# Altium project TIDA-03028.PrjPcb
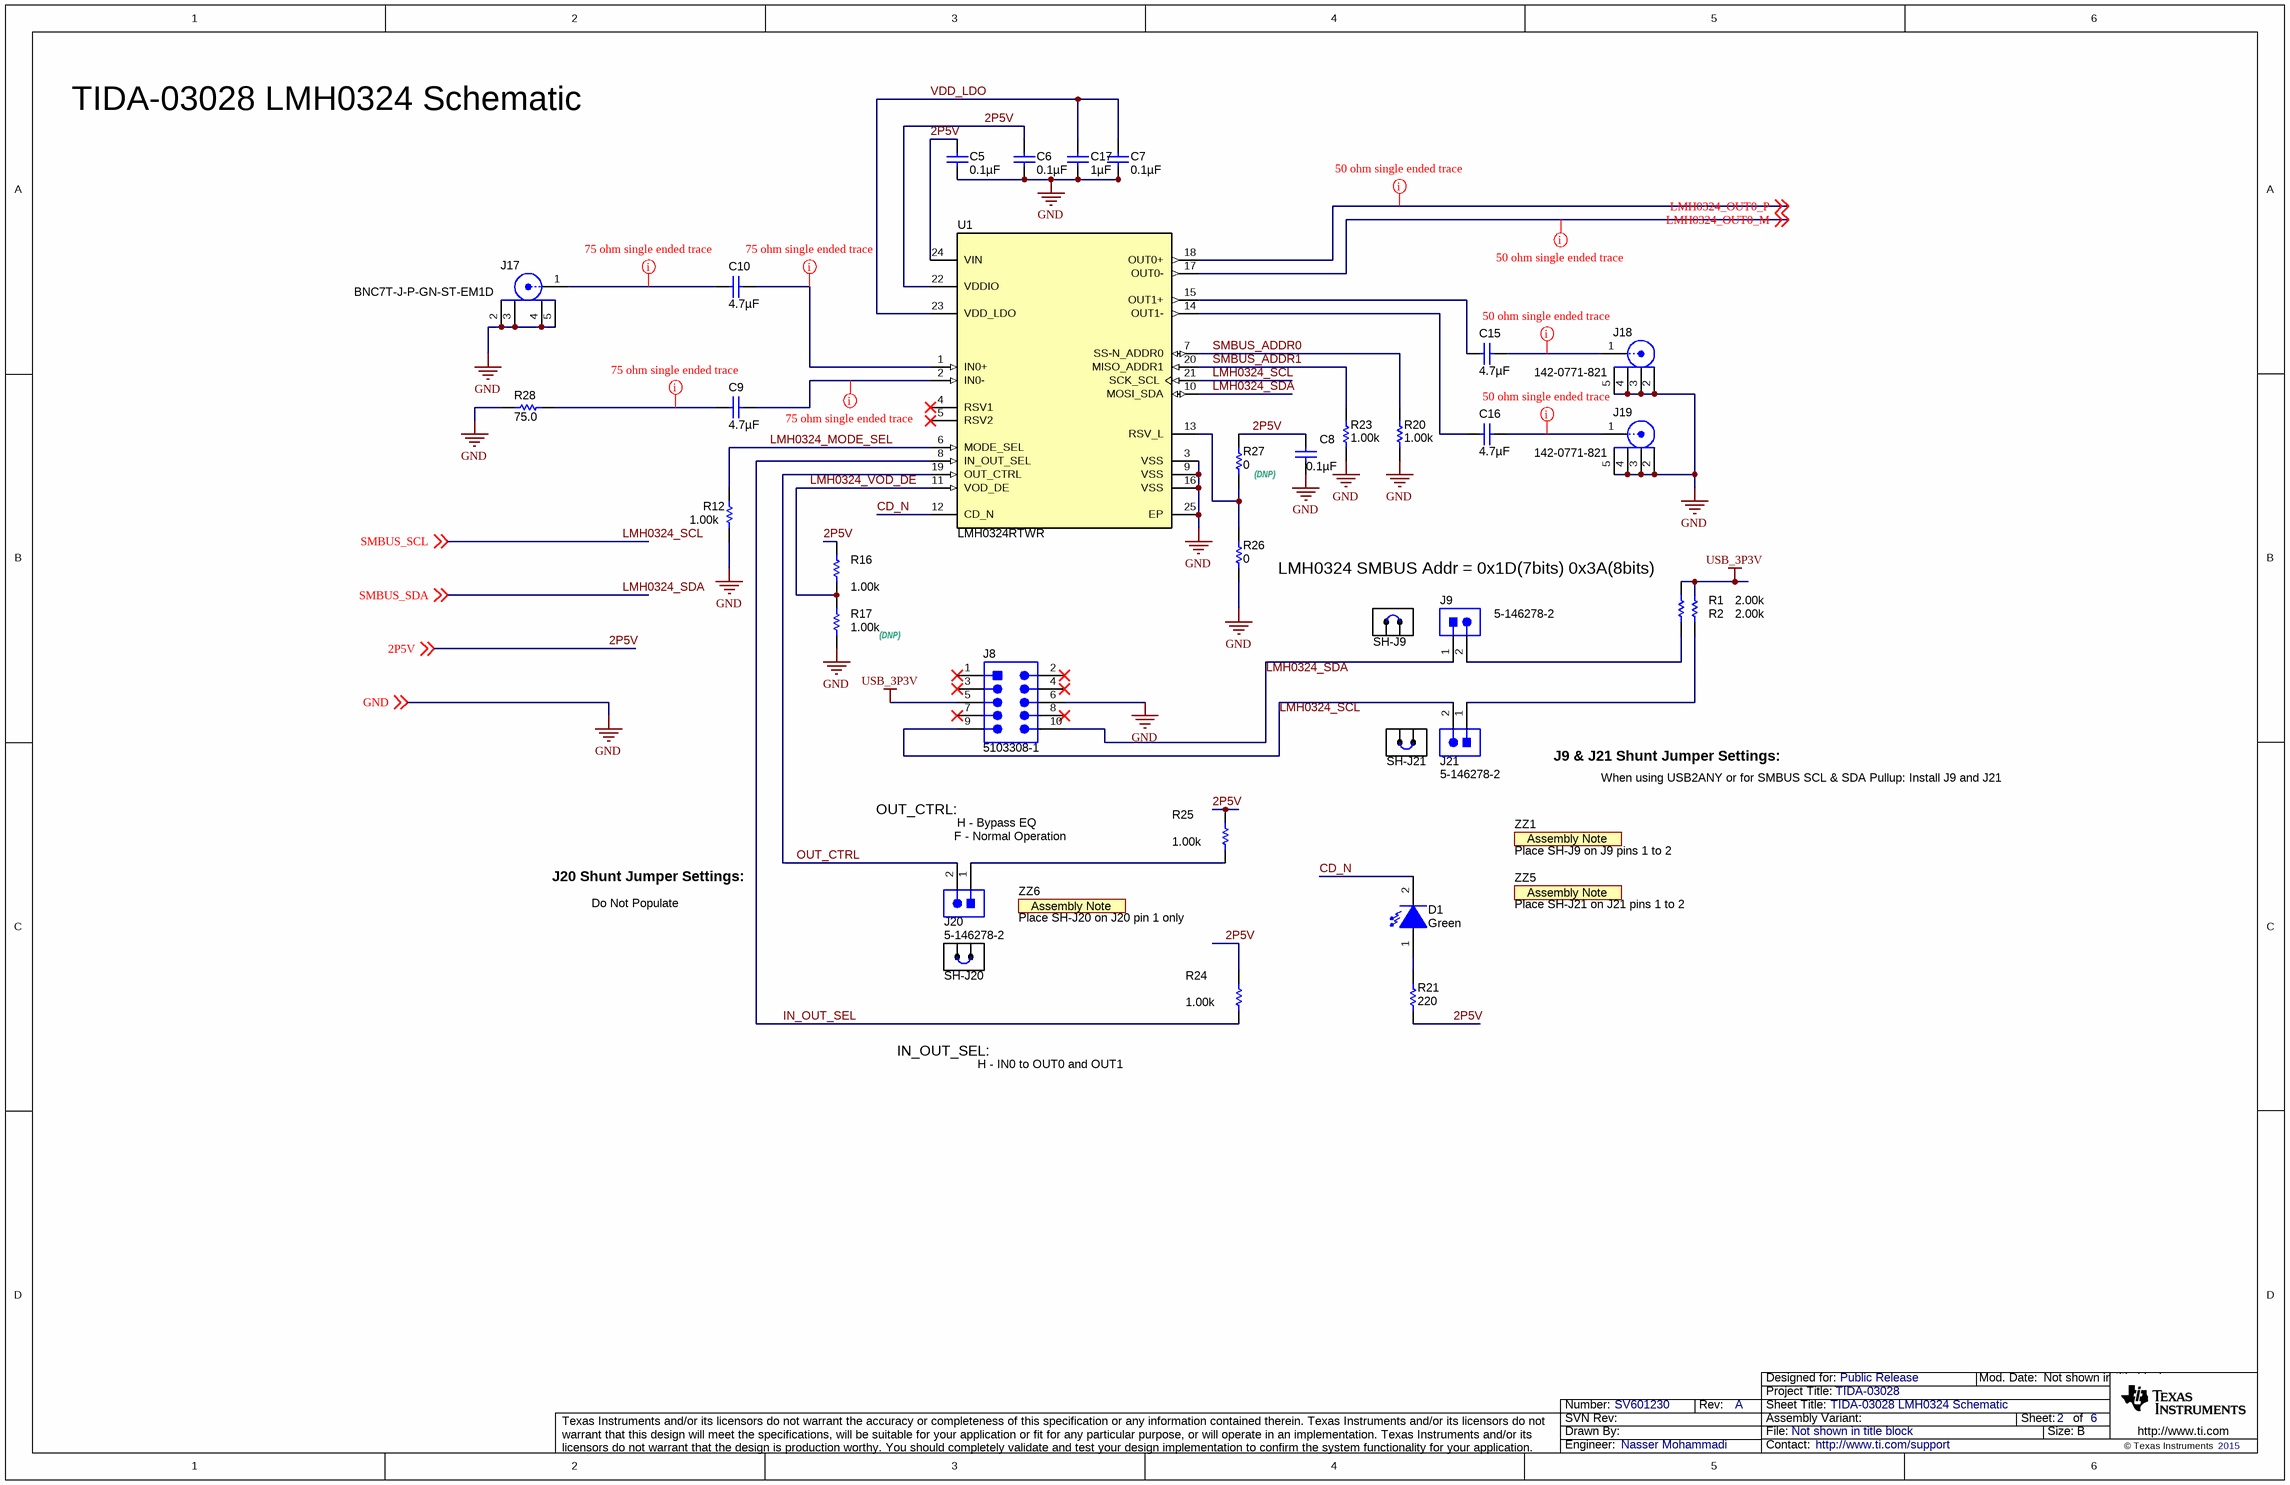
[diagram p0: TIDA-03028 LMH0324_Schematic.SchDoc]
TechSupport: http://www.ti.com/support; SCH_Rev: A; PRJ_Title: TIDA-03028; PRJ_Number: SV601230; PRJ_Engineer: Nasser Mohammadi; PRJ_Customer: Public Release; PCB_Rev: A; CopyrightYear: 2015
6 sheets, 129 parts. Net scope: global (net labels, ports and power ports of the same name join across sheets).
Sheets:
  TIDA-03028 LMH0324_Schematic.SchDoc
  TIDA-03028 USB_CNTRL.SchDoc
  TIDA-03028 LMH0318_Schematic.SchDoc
  TIDA-03028 Hardware.SchDoc
  TIDA-03028 Block Diagram.SchDoc
  TIDA-03028 Power.SchDoc

## Sheet TIDA-03028 LMH0324_Schematic.SchDoc: TIDA-03028 LMH0324 Schematic
size 431 x 279 mm; Date: Not shown in title block; ApprovedBy: Not shown in title block; CheckedBy: Not shown in title block; Author: Not shown in title block; CompanyName: Not shown in title block; Engineer: NasserM; Organization: Not shown in title block; Address1: Not shown in title block; Address2: Not shown in title block; Address3: Not shown in title block; Address4: Not shown in title block; DocumentNumber: 1; Revision: A; SheetNumber: 2; SheetTotal: 6; PageSetup: Record=PageOptions¦CenterHorizontal=True¦CenterVertical=True¦PrintScale=0.59¦XCorrection=1.00¦YCorrection=1.00¦PrintKind=0¦BorderSize=5000000¦LeftOffset=0¦BottomOffset=0¦Orientation=2¦PaperLength=1000¦PaperWidth=1000¦Scale=100¦PaperSource=15¦PrintQuality=600¦MediaType=1¦DitherType=10¦PaperKind=Letter¦PrintScaleMode=1

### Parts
C5  ValueDisplayed: 0.1µF  [0402]  (hidden comment: C1005X5R0J104K)
C6  ValueDisplayed: 0.1µF  [0402]  (hidden comment: C1005X5R0J104K)
C7  ValueDisplayed: 0.1µF  [0402]  (hidden comment: C1005X5R0J104K)
C8  ValueDisplayed: 0.1µF  [0402]  (hidden comment: C1005X5R0J104K)
C9  ValueDisplayed: 4.7µF  [0402S]  (hidden comment: C1005X5R1A475K050BC)
C10  ValueDisplayed: 4.7µF  [0402S]  (hidden comment: C1005X5R1A475K050BC)
C15  ValueDisplayed: 4.7µF  [0402S]  (hidden comment: C1005X5R1A475K050BC)
C16  ValueDisplayed: 4.7µF  [0402S]  (hidden comment: C1005X5R1A475K050BC)
C17  ValueDisplayed: 1µF  [0402]  (hidden comment: C1005X5R0J105M)
D1  value Green  [LED_SML-LX0603GW]  (hidden comment: SML-LX0603GW-TR)
J8  5103308-1  [CONN_5103308-1]
J9  5-146278-2  [TE_5-146278-2]
J17  BNC7T-J-P-GN-ST-EM1D  [SAMTEC_BNC7T-J-P-GN-ST-EM1D]
J18  142-0771-821  [Emerson_142-0771-821]
J19  142-0771-821  [Emerson_142-0771-821]
J20  5-146278-2  [TE_5-146278-2]
J21  5-146278-2  [TE_5-146278-2]
R1  value 2.00k  [0402]  (hidden comment: CRCW04022K00FKED)
R2  value 2.00k  [0402]  (hidden comment: CRCW04022K00FKED)
R12  value 1.00k  [0402]  (hidden comment: CRCW04021K00FKED)
R16  value 1.00k  [0402]  (hidden comment: Do Not Populate)
R17  value 1.00k  [0402]  (hidden comment: CRCW04021K00FKED)
R20  value 1.00k  [0402]  (hidden comment: CRCW04021K00FKED)
R21  value 220  [0402]  (hidden comment: CRCW0402220RJNED)
R23  value 1.00k  [0402]  (hidden comment: CRCW04021K00FKED)
R24  value 1.00k  [0402]  (hidden comment: CRCW04021K00FKED)
R25  value 1.00k  [0402]  (hidden comment: CRCW04021K00FKED)
R26  ValueDisplayed: 0  [0402]  (hidden comment: ERJ-2GE0R00X)
R27  ValueDisplayed: 0  [0402]  (hidden comment: Do Not Populate)
R28  value 75.0  [0402]  (hidden comment: CRCW040275R0FKED)
SH-J9  969102-0000-DA  [SNT-100-BK-G]  (value not drawn)
SH-J20  969102-0000-DA  [SNT-100-BK-G]  (value not drawn)
SH-J21  969102-0000-DA  [SNT-100-BK-G]  (value not drawn)
U1  LMH0324RTWR  [RTW0024A]
ZZ1  Place SH-J9 on J9 pins 1 to 2  [AssemblyNote]  (no BOM)
ZZ5  Place SH-J21 on J21 pins 1 to 2  [AssemblyNote]  (no BOM)
ZZ6  Place SH-J20 on J20 pin 1 only  [AssemblyNote]  (no BOM)

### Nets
2P5V: C5.1 C6.1 C8.1 R16.2 R21.1 R24.2 R25.2 R27.2 U1.22(VDDIO) U1.24(VIN) ; off-sheet 2P5V
GND: C5.2 C6.2 C7.2 C8.2 C17.2 J8.6 J17.2 J17.3 J17.4 J17.5 J18.2 J18.3 J18.4 J18.5 J19.2 J19.3 J19.4 J19.5 R12.1 R17.1 R20.1 R23.1 R26.1 R28.2 U1.3(VSS) U1.9(VSS) U1.16(VSS) U1.25(EP) ; off-sheet GND
USB_3P3V: J8.5 R1.2 R2.2
CD_N: D1.2(K) U1.12(CD_N)
IN_OUT_SEL: R24.1 U1.8(IN_OUT_SEL)
LMH0324_MODE_SEL: R12.2 U1.6(MODE_SEL)
LMH0324_OUT0_M: U1.17(OUT0-) ; off-sheet LMH0324_OUT0_M
LMH0324_OUT0_P: U1.18(OUT0+) ; off-sheet LMH0324_OUT0_P
LMH0324_SCL: J8.9 J21.2 U1.21(SCK_SCL) ; off-sheet SMBUS_SCL  [also labelled SMBUS_SCL]  [project net GPIO1/I2C_SCL]
LMH0324_SDA: J8.10 J9.1 U1.10(MOSI_SDA) ; off-sheet SMBUS_SDA  [also labelled SMBUS_SDA]  [project net GPIO0/I2C_SDA]
LMH0324_VOD_DE: R16.1 R17.2 U1.11(VOD_DE)
OUT_CTRL: J20.2 U1.19(OUT_CTRL)
SMBUS_ADDR0: R20.2 U1.7(SS-N_ADDR0)
SMBUS_ADDR1: R23.2 U1.20(MISO_ADDR1)
VDD_LDO: C7.1 C17.1 U1.23(VDD_LDO)
NetC9_1: C9.1 U1.2(IN0-)
NetC9_2: C9.2 R28.1
NetC10_1: C10.1 U1.1(IN0+)
NetC10_2: C10.2 J17.1
NetC15_1: C15.1 J18.1
NetC15_2: C15.2 U1.15(OUT1+)
NetC16_1: C16.1 J19.1
NetC16_2: C16.2 U1.14(OUT1-)
NetD1_1: D1.1(A) R21.2
NetJ9_2: J9.2 R1.1
NetJ20_1: J20.1 R25.1
NetJ21_1: J21.1 R2.1
NetR26_2: R26.2 R27.1 U1.13(RSV_L)

Not connected (* = marked no-connect by the designer): J8 1* 2* 3* 4* 7* 8*; U1 4(RSV1)* 5(RSV2)*

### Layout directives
rule Undefined: LMH0324_OUT0_M, LMH0324_OUT0_P, NetC9_1, NetC9_2, NetC10_1, NetC10_2, NetC15_1, NetC16_1

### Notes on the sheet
- TIDA-03028 LMH0324 Schematic
- (near R27) (DNP)
- LMH0324 SMBUS Addr = 0x1D(7bits) 0x3A(8bits)
- (DNP)
- J9 & J21 Shunt Jumper Settings:
- OUT_CTRL:
- H - Bypass EQ
- F - Normal Operation
- When using USB2ANY or for SMBUS SCL & SDA Pullup: Install J9 and J21
- Do Not Populate
- J20 Shunt Jumper Settings:
- IN_OUT_SEL:
- H - IN0 to OUT0 and OUT1

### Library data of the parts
C5-C8 = C1005X5R0J104K: CAP, CERM, 0.1uF, 6.3V, +/-10%, X5R, 0402; Manufacturer: TDK; Polarized: N; CompType: Capacitor; U/M: EA; Cap_F: 0.0000001; Tolerance_%: 10; ESR_Ohm: 0.0186; Value1: 0.0186 ohm; VDC_V: 6.3; TaMin_C: -55; TaMax_C: 85
C9 C10 C15 C16 = C1005X5R1A475K050BC: CAP, CERM, 4.7 µF, 10 V, +/- 10%, X5R, 0402; Manufacturer: TDK; Polarized: N; CompType: Capacitor; Value: 4.7uF; U/M: EA; Cap_F: 0.0000047; Tolerance_%: 10; Value1: Unknown; Value2: 10V; TaMin_C: -55; TaMax_C: 85; Cap_Case: 0402
C17 = C1005X5R0J105M: CAP, CERM, 1 µF, 6.3 V, +/- 20%, X5R, 0402; Manufacturer: TDK; Polarized: N; CompType: Capacitor; Value: 1uF; U/M: EA; Cap_F: 0.000001; Tolerance_%: 20; ESR_ohm: 0.0079; Value1: 0.0079 ohm; VDC_V: 6.3; Value2: 6.3V; TaMin_C: -55; TaMax_C: 85
D1 = SML-LX0603GW-TR: LED, Green, SMD; Manufacturer: Lumex; Vf_V: 2.2; Value2: 2.2V; Io_A: 0.02; Tjmax_C: 85; Value1: W; U/M: EA
J8 = 5103308-1: Header (shrouded), 100mil, 5x2, Gold, TH; Manufacturer: TE Connectivity; SymbolCreator: a0412235; U/M: EA
J9 J20 J21 = 5-146278-2: Header, 100mil, 2x1, Tin, TH; Manufacturer: TE Connectivity; SymbolCreator: a0412235; U/M: EA
J17 = BNC7T-J-P-GN-ST-EM1D: Connector, BNC Edge Mount, SMD; Manufacturer: Samtec; SymbolCreator: Altium; U/M: EA
J18 J19 = 142-0771-821: Connector, TH, End launch SMA 50 ohm; Manufacturer: Emerson Network Power; SymbolCreator: X0208326; U/M: EA
R1 R2 = CRCW04022K00FKED: RES, 2.00k ohm, 1%, 0.063W, 0402; Manufacturer: Vishay-Dale; CompType: Resistor; Res_ohm: 2000; Value_Code: 2k00; Tolerance_%: 1; Power_W: 0.063; VDC_V: 50; TempCo: 100 ppm/C; EIA_Code: E96; U/M: EA
R12 R16 R17 R20 R23-R25 = CRCW04021K00FKED: RES, 1.00k ohm, 1%, 0.063W, 0402; Manufacturer: Vishay-Dale; CompType: Resistor; Res_ohm: 1000; Value_Code: 1k00; Tolerance_%: 1; Power_W: 0.063; VDC_V: 50; TempCo: 100 ppm/C; EIA_Code: E96; U/M: EA
R21 = CRCW0402220RJNED: RES, 220 ohm, 5%, 0.063W, 0402; Manufacturer: Vishay-Dale; CompType: Resistor; Value_Code: 220R; Tolerance_%: 5; Power_W: 0.063; VDC_V: 50; TempCo: 200 ppm/C; EIA_Code: E24; U/M: EA
R26 R27 = ERJ-2GE0R00X: RES, 0, 5%, 0.063 W, 0402; Manufacturer: Panasonic; CompType: Resistor; Value_Code: 0000; Tolerance_%: 5; Power_W: 0.063; Value2: 0.063W; VDC_V: 50; TempCo: 600 ppm/C; EIA_Code: E24; U/M: EA; Value: 0; AEC Category: Q200
R28 = CRCW040275R0FKED: RES, 75.0 ohm, 1%, 0.063W, 0402; Manufacturer: Vishay-Dale; CompType: Resistor; Res_ohm: 75; Value_Code: 75R0; Tolerance_%: 1; Power_W: 0.063; VDC_V: 50; TempCo: 100 ppm/C; EIA_Code: E96; U/M: EA
SH-J9 SH-J20 SH-J21 = 969102-0000-DA: Shunt, 100mil, Gold plated, Black; Manufacturer: 3M; Alternate Manufacturer: Samtec; Value: 1x2; Note: You can "mate" this to a header by matching the designator.  i.e. use SH-J3 for header J3
U1 = LMH0324RTWR: 3G HD/SD SDI Adaptive Cable Equalizer, RTW0024A; Alternate PartNumber: LMH0324RTWT; Manufacturer: Texas Instruments; SymbolCreator: Altium; CompType: IC; U/M: EA
ZZ1 ZZ5 ZZ6 = AssemblyNote: SymbolCreator: codlsc

## Sheet TIDA-03028 USB_CNTRL.SchDoc: TIDA-03028 - USB_CNTRL
size 431 x 279 mm; Date: Not shown in title block; ApprovedBy: Not shown in title block; CheckedBy: Not shown in title block; Author: Not shown in title block; CompanyName: Not shown in title block; Engineer: Not shown in title block; Organization: Not shown in title block; Address1: Not shown in title block; Address2: Not shown in title block; Address3: Not shown in title block; Address4: Not shown in title block; DocumentNumber: 1; Revision: Use project parameter SCH_Rev; SheetNumber: 4; SheetTotal: 6; PageSetup: Record=PageOptions¦CenterHorizontal=True¦CenterVertical=True¦PrintScale=1.00¦XCorrection=1.00¦YCorrection=1.00¦PrintKind=0¦BorderSize=5000000¦LeftOffset=0¦BottomOffset=0¦Orientation=2¦PaperLength=1000¦PaperWidth=1000¦Scale=100¦PaperSource=15¦PrintQuality=600¦MediaType=1¦DitherType=10¦PaperKind=Letter¦PrintScaleMode=1
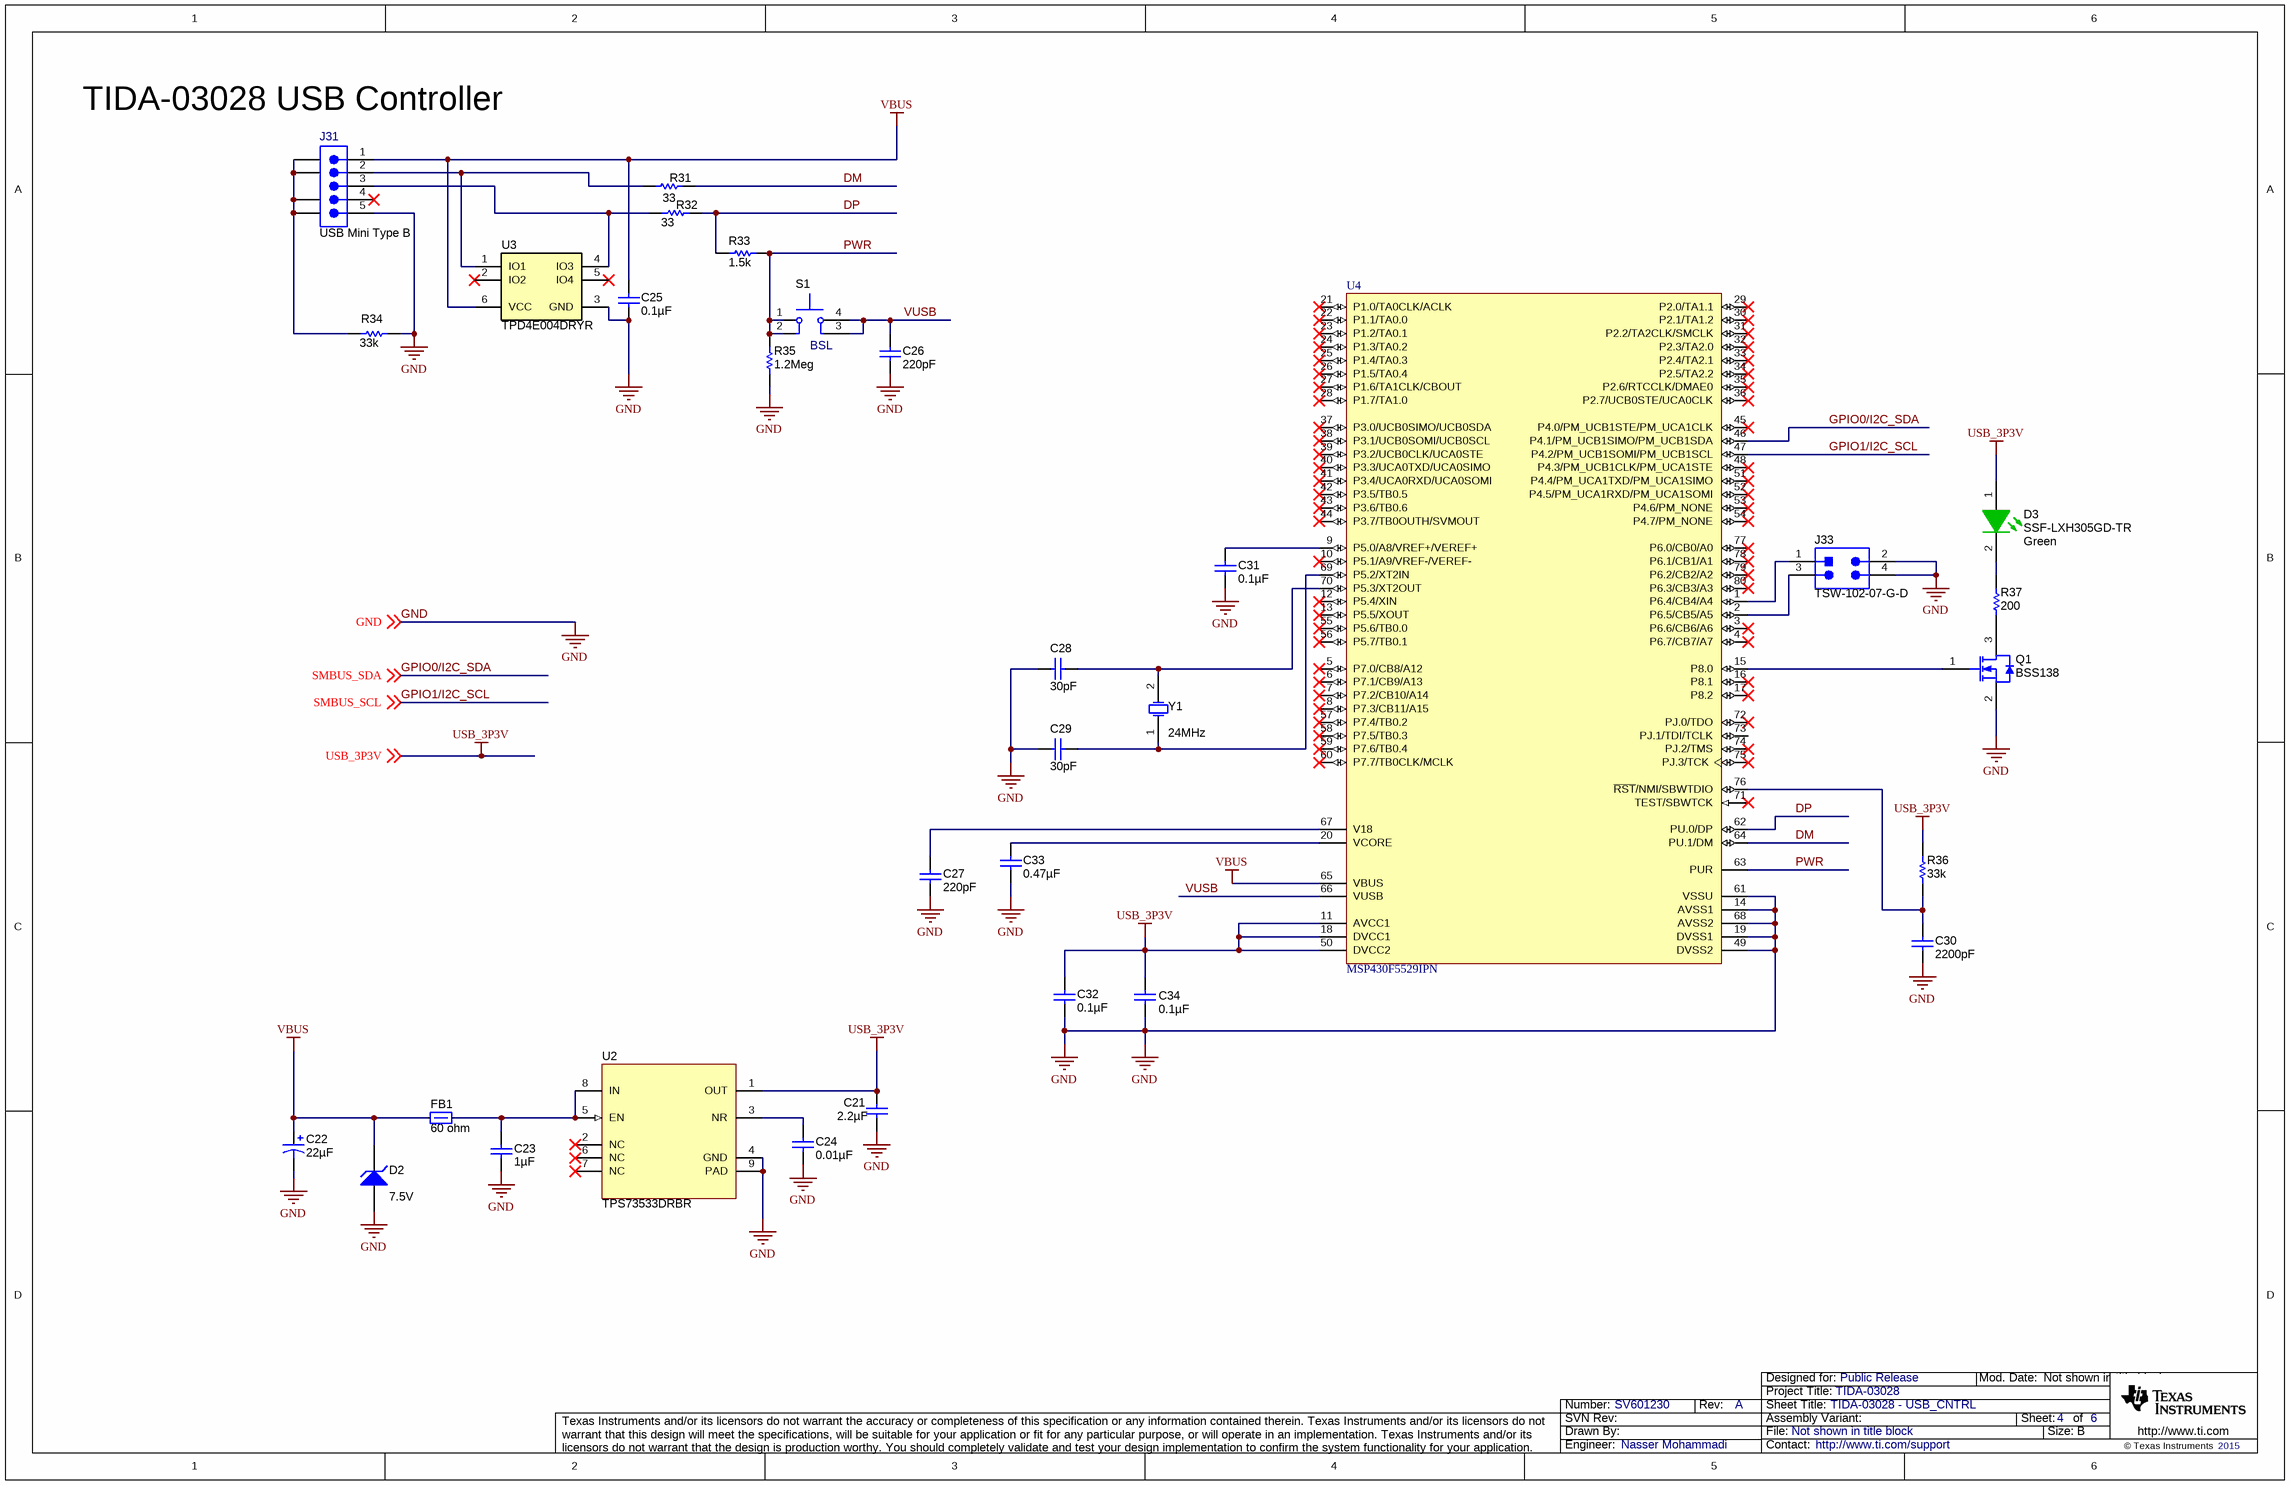
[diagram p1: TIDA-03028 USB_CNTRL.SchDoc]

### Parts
C21  ValueDisplayed: 2.2µF  [C0805]  (hidden comment: 0805YD225KAT2A)
C22  ValueDisplayed: 22µF  [CAPSMT_62_E55]  (hidden comment: EMVE100ADA220ME55G)
C23  ValueDisplayed: 1µF  [0805_HV]  (hidden comment: 0805YD105KAT2A)
C24  ValueDisplayed: 0.01µF  [C603]  (hidden comment: C1608X7R1H103K)
C25  ValueDisplayed: 0.1µF  [C603]  (hidden comment: 0603YC104JAT2A)
C26  ValueDisplayed: 220pF  [C603]  (hidden comment: 06035A221FAT2A)
C27  ValueDisplayed: 220pF  [C603]  (hidden comment: 06035A221FAT2A)
C28  ValueDisplayed: 30pF  [C603]  (hidden comment: GRM1885C2A300JA01D)
C29  ValueDisplayed: 30pF  [C603]  (hidden comment: GRM1885C2A300JA01D)
C30  ValueDisplayed: 2200pF  [C603]  (hidden comment: C0603X222K5RACTU)
C31  ValueDisplayed: 0.1µF  [C603]  (hidden comment: 0603YC104JAT2A)
C32  ValueDisplayed: 0.1µF  [C603]  (hidden comment: 0603YC104JAT2A)
C33  ValueDisplayed: 0.47µF  [C603]  (hidden comment: GRM188R71A474KA61D)
C34  ValueDisplayed: 0.1µF  [C603]  (hidden comment: 0603YC104JAT2A)
D2  value 7.5V  [SMB]  (hidden comment: 1SMB5922BT3G)
D3  SSF-LXH305GD-TR  value Green  [SSF-LXH305GD_Green]
FB1  value 60 ohm  [0603]  (hidden comment: BK1608HS600-T)
J31  USB Mini Type B  [CONN_USB-Mini-B-1734035-2]
J33  TSW-102-07-G-D  [TSW-102-07-G-D]
Q1  BSS138  [SOT-23]
R31  value 33  [0402]  (hidden comment: CRCW040233R0JNED)
R32  value 33  [0402]  (hidden comment: CRCW040233R0JNED)
R33  value 1.5k  [0402]  (hidden comment: CRCW04021K50JNED)
R34  value 33k  [0402]  (hidden comment: CRCW040233K0JNED)
R35  value 1.2Meg  [R603]  (hidden comment: CRCW06031M20JNEA)
R36  value 33k  [0402]  (hidden comment: CRCW040233K0JNED)
R37  value 200  [R603]  (hidden comment: CRCW0603200RFKEA)
S1  EVQ-PSD02K  [SW_EVQ-PSD02K]  (value not drawn)
U2  TPS73533DRBR  [DRB0008A]
U3  TPD4E004DRYR  [DRY0006A]
U4  MSP430F5529IPN  [PN0080A_N]
Y1  Frequency: 24MHz  [XTAL_CSM-7X]  (hidden comment: ECS-240-20-5PX-TR)

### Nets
GND: C21.1 C22.2(-) C23.1 C24.1 C25.1 C26.1 C27.1 C28.2 C29.2 C30.1 C31.1 C32.1 C33.1 C34.1 D2.2(A) J31.5 J33.2 J33.4 Q1.2(S) R34.1 R35.1 U2.4(GND) U2.9(PAD) U3.3(GND) U4.14(AVSS1) U4.19(DVSS1) U4.49(DVSS2) U4.61(VSSU) U4.68(AVSS2) ; off-sheet GND
USB_3P3V: C21.2 C32.2 C34.2 D3.1(A) R36.1 U2.1(OUT) U4.11(AVCC1) U4.18(DVCC1) U4.50(DVCC2) ; off-sheet USB_3P3V
VBUS: C22.1(+) C25.2 D2.1(K) FB1.1 J31.1 U3.6(VCC) U4.65(VBUS)
DM: R31.1 U4.64(PU.1/DM)
DP: R32.1 R33.2 U4.62(PU.0/DP)
GPIO0/I2C_SDA: U4.46(P4.1/PM_UCB1SIMO/PM_UCB1SDA) ; off-sheet SMBUS_SDA  [also labelled SMBUS_SDA]
GPIO1/I2C_SCL: U4.47(P4.2/PM_UCB1SOMI/PM_UCB1SCL) ; off-sheet SMBUS_SCL  [also labelled SMBUS_SCL]
PWR: R33.1 R35.2 S1.1 S1.2 U4.63(PUR)
VUSB: C26.2 S1.3 S1.4 U4.66(VUSB)
NetC23_2: C23.2 FB1.2 U2.5(EN) U2.8(IN)
NetC24_2: C24.2 U2.3(NR)
NetC27_2: C27.2 U4.67(V18)
NetC28_1: C28.1 U4.70(P5.3/XT2OUT) Y1.2(OSC2)
NetC29_1: C29.1 U4.69(P5.2/XT2IN) Y1.1(OSC1)
NetC30_2: C30.2 R36.2 U4.76(~{RST}/NMI/SBWTDIO)
NetC31_2: C31.2 U4.9(P5.0/A8/VREF+/VEREF+)
NetC33_2: C33.2 U4.20(VCORE)
NetD3_2: D3.2(K) R37.2
NetJ31_2: J31.2 R31.2 U3.1(IO1)
NetJ31_3: J31.3 R32.2 U3.4(IO3)
NetJ31_6: J31.6(GND) J31.7(GND) J31.8(GND) J31.9(GND) R34.2
NetJ33_1: J33.1 U4.1(P6.4/CB4/A4)
NetJ33_3: J33.3 U4.2(P6.5/CB5/A5)
NetQ1_1: Q1.1(G) U4.15(P8.0)
NetQ1_3: Q1.3(D) R37.1

Not connected (* = marked no-connect by the designer): J31 4*; U2 2(NC)* 6(NC)* 7(NC)*; U3 2(IO2)* 5(IO4)*; U4 3(P6.6/CB6/A6)* 4(P6.7/CB7/A7)* 5(P7.0/CB8/A12)* 6(P7.1/CB9/A13)* 7(P7.2/CB10/A14)* 8(P7.3/CB11/A15)* 10(P5.1/A9/VREF-/VEREF-)* 12(P5.4/XIN)* 13(P5.5/XOUT)* 16(P8.1)* 17(P8.2)* 21(P1.0/TA0CLK/ACLK)* 22(P1.1/TA0.0)* 23(P1.2/TA0.1)* 24(P1.3/TA0.2)* 25(P1.4/TA0.3)* 26(P1.5/TA0.4)* 27(P1.6/TA1CLK/CBOUT)* 28(P1.7/TA1.0)* 29(P2.0/TA1.1)* 30(P2.1/TA1.2)* 31(P2.2/TA2CLK/SMCLK)* 32(P2.3/TA2.0)* 33(P2.4/TA2.1)* 34(P2.5/TA2.2)* 35(P2.6/RTCCLK/DMAE0)* 36(P2.7/UCB0STE/UCA0CLK)* 37(P3.0/UCB0SIMO/UCB0SDA)* 38(P3.1/UCB0SOMI/UCB0SCL)* 39(P3.2/UCB0CLK/UCA0STE)* 40(P3.3/UCA0TXD/UCA0SIMO)* 41(P3.4/UCA0RXD/UCA0SOMI)* 42(P3.5/TB0.5)* 43(P3.6/TB0.6)* 44(P3.7/TB0OUTH/SVMOUT)* 45(P4.0/PM_UCB1STE/PM_UCA1CLK)* 48(P4.3/PM_UCB1CLK/PM_UCA1STE)* 51(P4.4/PM_UCA1TXD/PM_UCA1SIMO)* 52(P4.5/PM_UCA1RXD/PM_UCA1SOMI)* 53(P4.6/PM_NONE)* 54(P4.7/PM_NONE)* 55(P5.6/TB0.0)* 56(P5.7/TB0.1)* 57(P7.4/TB0.2)* 58(P7.5/TB0.3)* 59(P7.6/TB0.4)* 60(P7.7/TB0CLK/MCLK)* 71(TEST/SBWTCK)* 72(PJ.0/TDO)* 73(PJ.1/TDI/TCLK) 74(PJ.2/TMS)* 75(PJ.3/TCK)* 77(P6.0/CB0/A0)* 78(P6.1/CB1/A1)* 79(P6.2/CB2/A2)* 80(P6.3/CB3/A3)*

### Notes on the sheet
- (near J31) TIDA-03028 USB Controller
- (near S1) BSL

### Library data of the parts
C21 = 0805YD225KAT2A: CAP, CERM, 2.2uF, 16V, +/-10%, X5R, 0805; Manufacturer: AVX; Polarized: N; CompType: Capacitor; U/M: EA; Cap_F: 0.0000022; Tolerance_%: 10; ESR_Ohm: 0.009; Value1: 0.009 ohm; VDC_V: 16; TaMin_C: -55; TaMax_C: 85; Cap_Case: 0805
C22 = EMVE100ADA220ME55G: CAP ALUM 22UF 10V 20% SMD; Manufacturer: Panasonic - ECG; Polarized: Y; CompType: Capacitor; U/M: EA; Cap_F: 0.000022; Tolerance_%: 20; VDC_V: 10; IRMS_A: 0.03; TaMin_C: -40; TaMax_C: 105; Cap_Case: E55
C23 = 0805YD105KAT2A: CAP, CERM, 1 µF, 16 V, +/- 10%, X5R, 0805; Manufacturer: AVX; Polarized: N; CompType: Capacitor; Value: 1uF; U/M: EA; Cap_F: 0.000001; Tolerance_%: 10; ESR_ohm: 0.012; Value1: 0.012 ohm; VDC_V: 16; Value2: 16V; TaMin_C: -55; TaMax_C: 85; Cap_Case: 0805; AEC Category: Q200
C24 = C1608X7R1H103K: CAP, CERM, 0.01uF, 50V, +/-10%, X7R, 0603; Manufacturer: TDK; Polarized: N; CompType: Capacitor; U/M: EA; Cap_F: 0.00000001; Tolerance_%: 10; ESR_Ohm: 0.0539; Value1: 0.0539 ohm; VDC_V: 50; TaMin_C: -55; TaMax_C: 125; Cap_Case: 0603
C25 C31 C32 C34 = 0603YC104JAT2A: CAP, CERM, 0.1uF, 16V, +/-5%, X7R, 0603; Manufacturer: AVX; Polarized: N; CompType: Capacitor; U/M: EA; Cap_F: 0.0000001; Tolerance_%: 5; ESR_Ohm: 0.039; Value1: 0.039 ohm; VDC_V: 16; TaMin_C: -55; TaMax_C: 125; Cap_Case: 0603
C26 C27 = 06035A221FAT2A: CAP, CERM, 220pF, 50V, +/-1%, C0G/NP0, 0603; Manufacturer: AVX; Polarized: N; CompType: Capacitor; U/M: EA; Cap_F: 0.00000000022; Tolerance_%: 1; ESR_Ohm: 0.083; Value1: 0.083 ohm; VDC_V: 50; TaMin_C: -55; TaMax_C: 125; Cap_Case: 0603
C28 C29 = GRM1885C2A300JA01D: CAP, CERM, 30pF, 100V, +/-5%, C0G/NP0, 0603; Manufacturer: MuRata; Polarized: N; CompType: Capacitor; U/M: EA; Cap_F: 0.00000000003; Tolerance_%: 5; VDC_V: 100; TaMin_C: -55; TaMax_C: 125; Cap_Case: 0603
C30 = C0603X222K5RACTU: CAP, CERM, 2200pF, 50V, +/-10%, X7R, 0603; Manufacturer: Kemet; Polarized: N; CompType: Capacitor; U/M: EA; Cap_F: 0.0000000022; Tolerance_%: 10; VDC_V: 50; TaMin_C: -55; TaMax_C: 125; Cap_Case: 0603
C33 = GRM188R71A474KA61D: CAP, CERM, 0.47uF, 10V, +/-10%, X7R, 0603; Manufacturer: MuRata; Polarized: N; CompType: Capacitor; U/M: EA; Cap_F: 0.00000047; Tolerance_%: 10; TaMin_C: -55; TaMax_C: 125; Cap_Case: 0603
D2 = 1SMB5922BT3G: Diode, Zener, 7.5 V, 550 mW, SMB; Manufacturer: ON Semiconductor; SymbolCreator: a0412235; U/M: EA; Power_W: 0.55; Vz_V: 7.5; Value1: 0.55W; RJA_CperW: 226
D3 = SSF-LXH305GD-TR: LED, Green, SMD; Manufacturer: Lumex; SymbolCreator: Altium; Vf_V: 2.2; Value2: 2.2V; Io_A: 0.02; Vr_V: 5; Ir_A: 0.0001; Tjmax_C: 85; Value1: W; Angle: 60; U/M: EA
FB1 = BK1608HS600-T: Ferrite Bead, 60 ohm @ 100 MHz, 0.8 A, 0603; Manufacturer: Taiyo Yuden; Imax_A: 0.8; DCR_ohm: 0.1; Value1: 0.1 ohm; Value2: 0.8A; ZTyp@100MHz_Ohm: 60
J31 = 1734035-2: Connector, Receptacle, Mini-USB Type B, R/A, Top Mount SMT; Manufacturer: TE Connectivity; SymbolCreator: A0412235; U/M: EA
J33 = TSW-102-07-G-D: Header, 100mil, 2x2, Gold, TH; Manufacturer: Samtec; SymbolCreator: a0412235; U/M: EA
Q1 = BSS138: MOSFET, N-CH, 50 V, 0.22 A, SOT-23; Manufacturer: Fairchild Semiconductor; Alternate Manufacturer: None; U/M: EA; ChType: N; Value: 50V; VdsMax_V: 50; Value1: 6 ohm; Rdson45_ohm: 6; Value2: 1.7 nC; QgTyp_nC: 1.7; Vgs_V: 20; IdsMax_A: 0.22
R31 R32 = CRCW040233R0JNED: RES, 33 ohm, 5%, 0.063W, 0402; Manufacturer: Vishay-Dale; CompType: Resistor; Value_Code: 33R0; Tolerance_%: 5; Power_W: 0.063; VDC_V: 50; TempCo: 200 ppm/C; EIA_Code: E24; U/M: EA
R33 = CRCW04021K50JNED: RES, 1.5k ohm, 5%, 0.063W, 0402; Manufacturer: Vishay-Dale; CompType: Resistor; Res_ohm: 1500; Value_Code: 1k50; Tolerance_%: 5; Power_W: 0.063; VDC_V: 50; TempCo: 200 ppm/C; EIA_Code: E24; U/M: EA
R34 R36 = CRCW040233K0JNED: RES, 33k ohm, 5%, 0.063W, 0402; Manufacturer: Vishay-Dale; CompType: Resistor; Res_ohm: 33000; Value_Code: 33k0; Tolerance_%: 5; Power_W: 0.063; VDC_V: 50; TempCo: 200 ppm/C; EIA_Code: E24; U/M: EA
R35 = CRCW06031M20JNEA: RES, 1.2Meg ohm, 5%, 0.1W, 0603; Manufacturer: Vishay-Dale; CompType: Resistor; Res_ohm: 1200000; Value_Code: 1M20; Tolerance_%: 5; Power_W: 0.1; VDC_V: 75; TempCo: 200 ppm/C; EIA_Code: E24; U/M: EA
R37 = CRCW0603200RFKEA: RES, 200 ohm, 1%, 0.1W, 0603; Manufacturer: Vishay-Dale; CompType: Resistor; Value_Code: 200R; Tolerance_%: 1; Power_W: 0.1; VDC_V: 75; TempCo: 100 ppm/C; EIA_Code: E96; U/M: EA
S1 = EVQ-PSD02K: Switch, Tactile, SPST-NO, SMT; Manufacturer: Panasonic; SymbolCreator: a0799628; VDC_V: 12; SwitchFunction: Off-Mom; PositionCount: 1; CurrentRating_mA: 50
U2 = TPS73533DRBR: 500mA, Low Quiescent Current, Ultra-Low Noise, High PSRR Low-Dropout Linear Regulator, DRB0008A; Manufacturer: Texas Instruments; Alternate PartNumber: TPS73533DRBT; SymbolCreator: Altium; CompType: IC; U/M: EA
U3 = TPD4E004DRYR: ESD-Protection Array for High-Speed Data Interfaces, 4 Channels, -40 to +85 degC, 6-pin SON (DRY), Green (RoHS & no Sb/Br); Manufacturer: Texas Instruments; Alternate PartNumber: Equivalent; 1394 / Firewire: TRUE; Breakdown Voltage(Min)(V): 6; IEC 61000-4-2 Air-Gap(+/- kV): 12; IEC 61000-4-2 Contact(+/- kV): 8; IO Capacitance(Typ)(pF): 1.6; IO Leakage Current(nA): 1; SubFamily: ESD Solution
U4 = MSP430F5529IPN: 25 MHz Mixed Signal Microcontroller with 128 KB Flash, 8192 B SRAM and 63 GPIOs, -40 to 85 degC, 80-pin QFP (PN), Green (RoHS & no Sb/Br); Manufacturer: Texas Instruments; Alternate PartNumber: Equivalent; ADC: 12-bit SAR; ADC Channels: 16; Brown Out Reset: Yes; DMA: 3; Flash(KB): 128; Frequency(MHz): 25; GPIO: 63; Multiplier: 32x32; Pin/Package: 0DIESALE, 80LQFP; SRAM(B): 8192; SubFamily: 5 Series; Timers - 16-bit: 4; USB: 1; USCI_A (UART/LIN/IrDA/SPI): 2
Y1 = ECS-240-20-5PX-TR: Crystal, 24.000MHz, 20pF, SMD; Manufacturer: ECS Inc.; SymbolCreator: a0412235; U/M: EA; TaMin_C: -10; TaMax_C: 70; Frequency Stability: ±50ppm

## Sheet TIDA-03028 LMH0318_Schematic.SchDoc: TIDA-03028 LMH0318_Schematic
size 431 x 279 mm; Date: Not shown in title block; ApprovedBy: Not shown in title block; CheckedBy: Not shown in title block; Author: Not shown in title block; CompanyName: Not shown in title block; Engineer: Nasser; Organization: Not shown in title block; Address1: Not shown in title block; Address2: Not shown in title block; Address3: Not shown in title block; Address4: Not shown in title block; DocumentNumber: 1; Revision: Use project parameter SCH_Rev; SheetNumber: 3; SheetTotal: 6; PageSetup: Record=PageOptions¦CenterHorizontal=True¦CenterVertical=True¦PrintScale=1.00¦XCorrection=1.00¦YCorrection=1.00¦PrintKind=0¦BorderSize=5000000¦LeftOffset=0¦BottomOffset=0¦Orientation=2¦PaperLength=1000¦PaperWidth=1000¦Scale=100¦PaperSource=15¦PrintQuality=600¦MediaType=1¦DitherType=10¦PaperKind=Letter¦PrintScaleMode=1
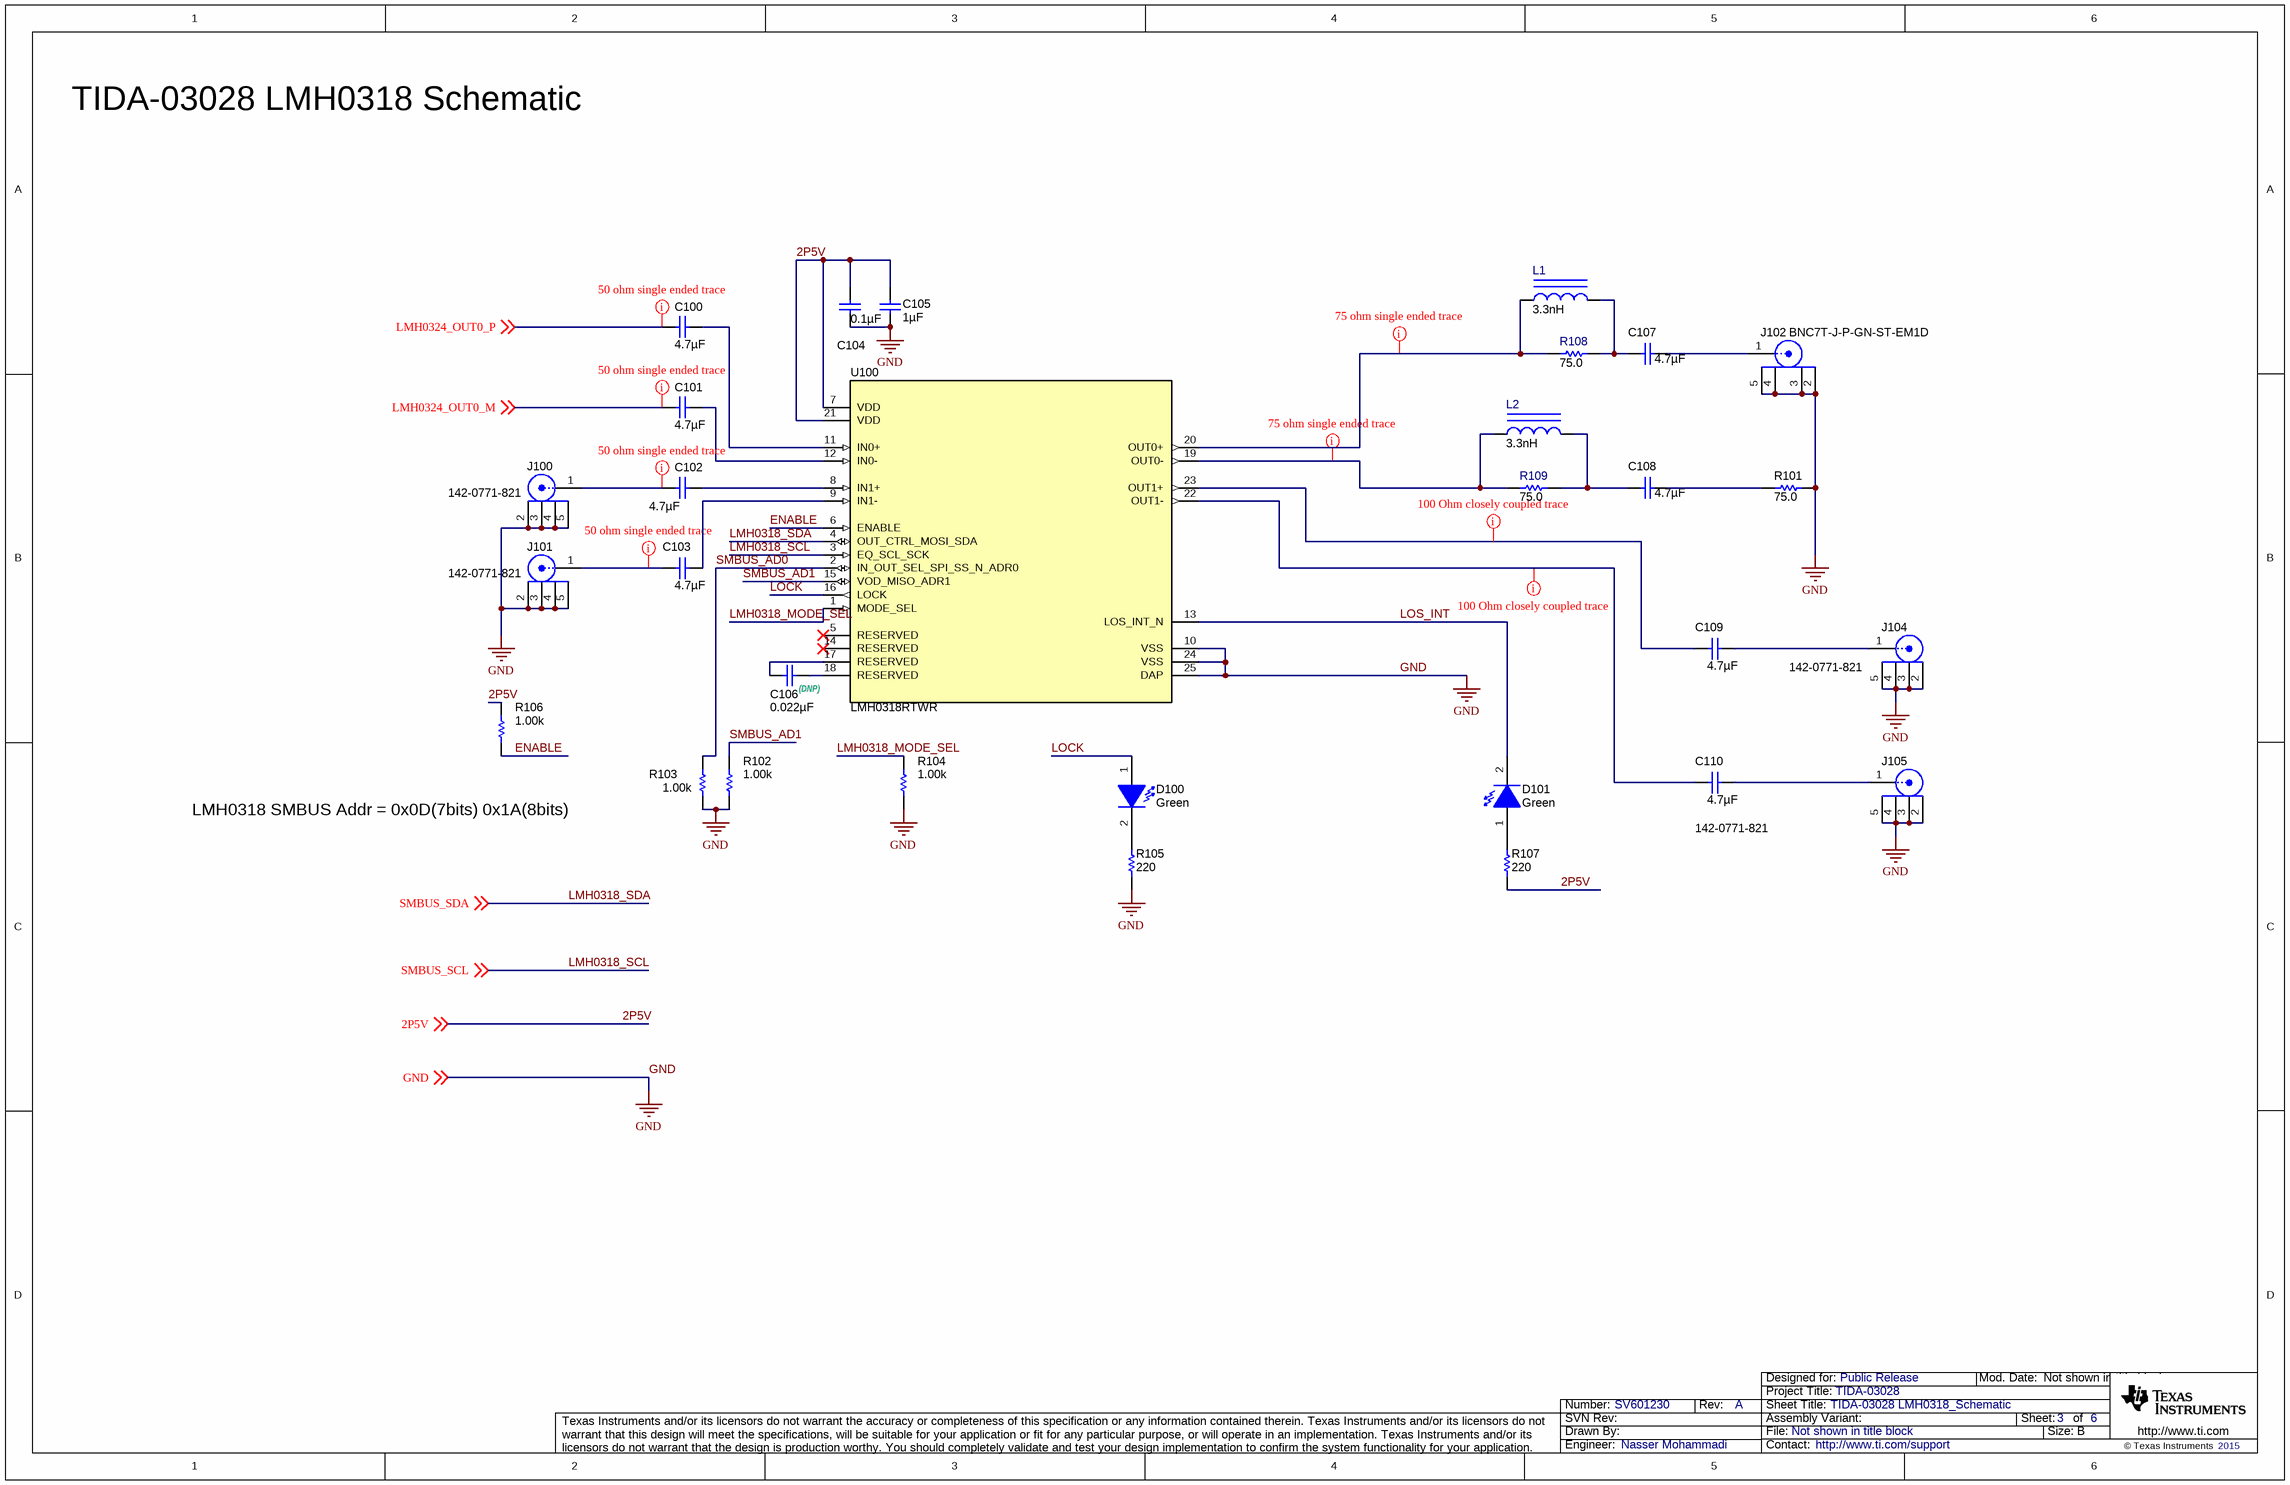
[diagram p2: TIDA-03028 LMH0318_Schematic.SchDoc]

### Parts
C100  ValueDisplayed: 4.7µF  [0402]  (hidden comment: C1005X5R0J475M050BC)
C101  ValueDisplayed: 4.7µF  [0402]  (hidden comment: C1005X5R0J475M050BC)
C102  ValueDisplayed: 4.7µF  [0402]  (hidden comment: C1005X5R0J475M050BC)
C103  ValueDisplayed: 4.7µF  [0402]  (hidden comment: C1005X5R0J475M050BC)
C104  ValueDisplayed: 0.1µF  [0402]  (hidden comment: C1005X5R0J104K)
C105  ValueDisplayed: 1µF  [0402]  (hidden comment: C1005X5R0J105M)
C106  ValueDisplayed: 0.022µF  [0402]  (hidden comment: Do Not Populate)
C107  ValueDisplayed: 4.7µF  [0402]  (hidden comment: C1005X5R0J475M050BC)
C108  ValueDisplayed: 4.7µF  [0402]  (hidden comment: C1005X5R0J475M050BC)
C109  ValueDisplayed: 4.7µF  [0402]  (hidden comment: C1005X5R0J475M050BC)
C110  ValueDisplayed: 4.7µF  [0402]  (hidden comment: C1005X5R0J475M050BC)
D100  value Green  [LED_SML-LX0603GW]  (hidden comment: SML-LX0603GW-TR)
D101  value Green  [LED_SML-LX0603GW]  (hidden comment: SML-LX0603GW-TR)
J100  142-0771-821  [Emerson_142-0771-821]
J101  142-0771-821  [Emerson_142-0771-821]
J102  BNC7T-J-P-GN-ST-EM1D  [SAMTEC_BNC7T-J-P-GN-ST-EM1D]
J104  142-0771-821  [Emerson_142-0771-821]
J105  142-0771-821  [Emerson_142-0771-821]
L1  ValueDisplayed: 3.3nH  [IND_LQG15H]  (hidden comment: LQG15HS3N3S02D)
L2  ValueDisplayed: 3.3nH  [IND_LQG15H]  (hidden comment: LQG15HS3N3S02D)
R101  value 75.0  [0402]  (hidden comment: CRCW040275R0FKED)
R102  value 1.00k  [0402]  (hidden comment: CRCW04021K00FKED)
R103  value 1.00k  [0402]  (hidden comment: CRCW04021K00FKED)
R104  value 1.00k  [0402]  (hidden comment: CRCW04021K00FKED)
R105  value 220  [0402]  (hidden comment: CRCW0402220RJNED)
R106  value 1.00k  [0402]  (hidden comment: CRCW04021K00FKED)
R107  value 220  [0402]  (hidden comment: CRCW0402220RJNED)
R108  ValueDisplayed: 75.0  [0402]  (hidden comment: CRCW040275R0FKED)
R109  ValueDisplayed: 75.0  [0402]  (hidden comment: CRCW040275R0FKED)
U100  LMH0318RTWR  [RTW0024A]

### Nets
2P5V: C104.1 C105.1 R106.2 R107.1 U100.7(VDD) U100.21(VDD) ; off-sheet 2P5V
GND: C104.2 C105.2 J100.2 J100.3 J100.4 J100.5 J101.2 J101.3 J101.4 J101.5 J102.2 J102.3 J102.4 J102.5 J104.2 J104.3 J104.4 J104.5 J105.2 J105.3 J105.4 J105.5 R101.1 R102.1 R103.1 R104.1 R105.1 U100.10(VSS) U100.24(VSS) U100.25(DAP) ; off-sheet GND
ENABLE: R106.1 U100.6(ENABLE)
LMH0318_MODE_SEL: R104.2 U100.1(MODE_SEL)
LMH0318_SCL: U100.3(EQ_SCL_SCK) ; off-sheet SMBUS_SCL  [also labelled SMBUS_SCL]  [project net GPIO1/I2C_SCL]
LMH0318_SDA: U100.4(OUT_CTRL_MOSI_SDA) ; off-sheet SMBUS_SDA  [also labelled SMBUS_SDA]  [project net GPIO0/I2C_SDA]
LMH0324_OUT0_M: C101.2 ; off-sheet LMH0324_OUT0_M
LMH0324_OUT0_P: C100.2 ; off-sheet LMH0324_OUT0_P
LOCK: D100.1(A) U100.16(LOCK)
LOS_INT: D101.2(K) U100.13(LOS_INT_N)
SMBUS_AD0: R103.2 U100.2(IN_OUT_SEL_SPI_SS_N_ADR0)
SMBUS_AD1: R102.2 U100.15(VOD_MISO_ADR1)
NetC100_1: C100.1 U100.11(IN0+)
NetC101_1: C101.1 U100.12(IN0-)
NetC102_1: C102.1 U100.8(IN1+)
NetC102_2: C102.2 J100.1
NetC103_1: C103.1 U100.9(IN1-)
NetC103_2: C103.2 J101.1
NetC106_1: C106.1 U100.18(RESERVED)
NetC106_2: C106.2 U100.17(RESERVED)
NetC107_1: C107.1 J102.1
NetC107_2: C107.2 L1.2 R108.2
NetC108_1: C108.1 R101.2
NetC108_2: C108.2 L2.2 R109.2
NetC109_1: C109.1 J104.1
NetC109_2: C109.2 U100.23(OUT1+)
NetC110_1: C110.1 J105.1
NetC110_2: C110.2 U100.22(OUT1-)
NetD100_2: D100.2(K) R105.2
NetD101_1: D101.1(A) R107.2
NetL1_1: L1.1 R108.1 U100.20(OUT0+)
NetL2_1: L2.1 R109.1 U100.19(OUT0-)

Not connected (* = marked no-connect by the designer): U100 5(RESERVED)* 14(RESERVED)*

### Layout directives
rule Undefined: LMH0324_OUT0_M, LMH0324_OUT0_P, NetC102_2, NetC103_2, NetC109_2, NetC110_2, NetL1_1, NetL2_1

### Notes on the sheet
- TIDA-03028 LMH0318 Schematic
- (near C106) (DNP)
- LMH0318 SMBUS Addr = 0x0D(7bits) 0x1A(8bits)

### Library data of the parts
C100-C103 C107-C110 = C1005X5R0J475M050BC: CAP, CERM, 4.7uF, 6.3V, +/-20%, X5R, 0402; Manufacturer: TDK; Polarized: N; CompType: Capacitor; U/M: EA; Cap_F: 0.0000047; Tolerance_%: 20; Value1: Unknown; VDC_V: 6.3; TaMin_C: -55; TaMax_C: 85
C104 = C1005X5R0J104K: as C5 on sheet TIDA-03028 LMH0324_Schematic
C105 = C1005X5R0J105M: CAP, CERM, 1 µF, 6.3 V, +/- 20%, X5R, 0402; Manufacturer: TDK; Polarized: N; CompType: Capacitor; Value: 1uF; U/M: EA; Cap_F: 0.000001; Tolerance_%: 20; ESR_ohm: 0.0079; Value1: 0.0079 ohm; VDC_V: 6.3; Value2: 6.3V; TaMin_C: -55; TaMax_C: 85; AEC Category: Q200
C106 = GRM155R61C223KA01D: CAP, CERM, 0.022uF, 16V, +/-10%, X5R, 0402; Manufacturer: MuRata; Polarized: N; CompType: Capacitor; U/M: EA; Cap_F: 0.000000022; Tolerance_%: 10; Value1: Unknown; VDC_V: 16; TaMin_C: -55; TaMax_C: 85
D100 D101 = SML-LX0603GW-TR: as D1 on sheet TIDA-03028 LMH0324_Schematic
J100 J101 J104 J105 = 142-0771-821: as J18 on sheet TIDA-03028 LMH0324_Schematic
J102 = BNC7T-J-P-GN-ST-EM1D: as J17 on sheet TIDA-03028 LMH0324_Schematic
L1 L2 = LQG15HS3N3S02D: Inductor, Multilayer, Air Core, 3.3 nH, 0.3 A, 0.17 ohm, SMD; Manufacturer: MuRata; Value: 3.3nH; Ind_H: 3.3E-9; Imax_A: 0.3; Irms: 0.3A @ C rise; Isat: 0.3A @ % inductance drop; DCR_ohm: 0.17; Value2: 0.3A; AEC Category: Q200
R101 = CRCW040275R0FKED: as R28 on sheet TIDA-03028 LMH0324_Schematic
R102-R104 R106 = CRCW04021K00FKED: as R12 on sheet TIDA-03028 LMH0324_Schematic
R105 R107 = CRCW0402220RJNED: as R21 on sheet TIDA-03028 LMH0324_Schematic
R108 R109 = CRCW040275R0FKED: RES, 75.0, 1%, 0.063 W, 0402; Manufacturer: Vishay-Dale; CompType: Resistor; Value: 75.0; Res_ohm: 75; Value_Code: 75R0; Tolerance_%: 1; Power_W: 0.063; Value2: 0.063W; VDC_V: 50; TempCo: 100 ppm/C; EIA_Code: E96; U/M: EA; AEC Category: Q200
U100 = LMH0318RTWR: Low Power Ultra HD Cable Driver with Integrated Reclocker, RTW0024A; Alternate Manufacturer: Texas Instruments; Alternate PartNumber: MH0318RTWT; SymbolCreator: Altium; CompType: IC; U/M: EA

## Sheet TIDA-03028 Hardware.SchDoc: TIDA-03028 Hardware
size 431 x 279 mm; Date: Not shown in title block; ApprovedBy: Not shown in title block; CheckedBy: Not shown in title block; Author: Not shown in title block; CompanyName: Not shown in title block; Engineer: Not shown in title block; Organization: Not shown in title block; Address1: Not shown in title block; Address2: Not shown in title block; Address3: Not shown in title block; Address4: Not shown in title block; DocumentNumber: 1; Revision: Use project parameter SCH_Rev; SheetNumber: 6; SheetTotal: 6; PageSetup: Record=PageOptions¦CenterHorizontal=True¦CenterVertical=True¦PrintScale=0.59¦XCorrection=1.00¦YCorrection=1.00¦PrintKind=0¦BorderSize=5000000¦LeftOffset=0¦BottomOffset=0¦Orientation=2¦PaperLength=1000¦PaperWidth=1000¦Scale=100¦PaperSource=15¦PrintQuality=600¦MediaType=1¦DitherType=10¦PaperKind=Letter¦PrintScaleMode=1
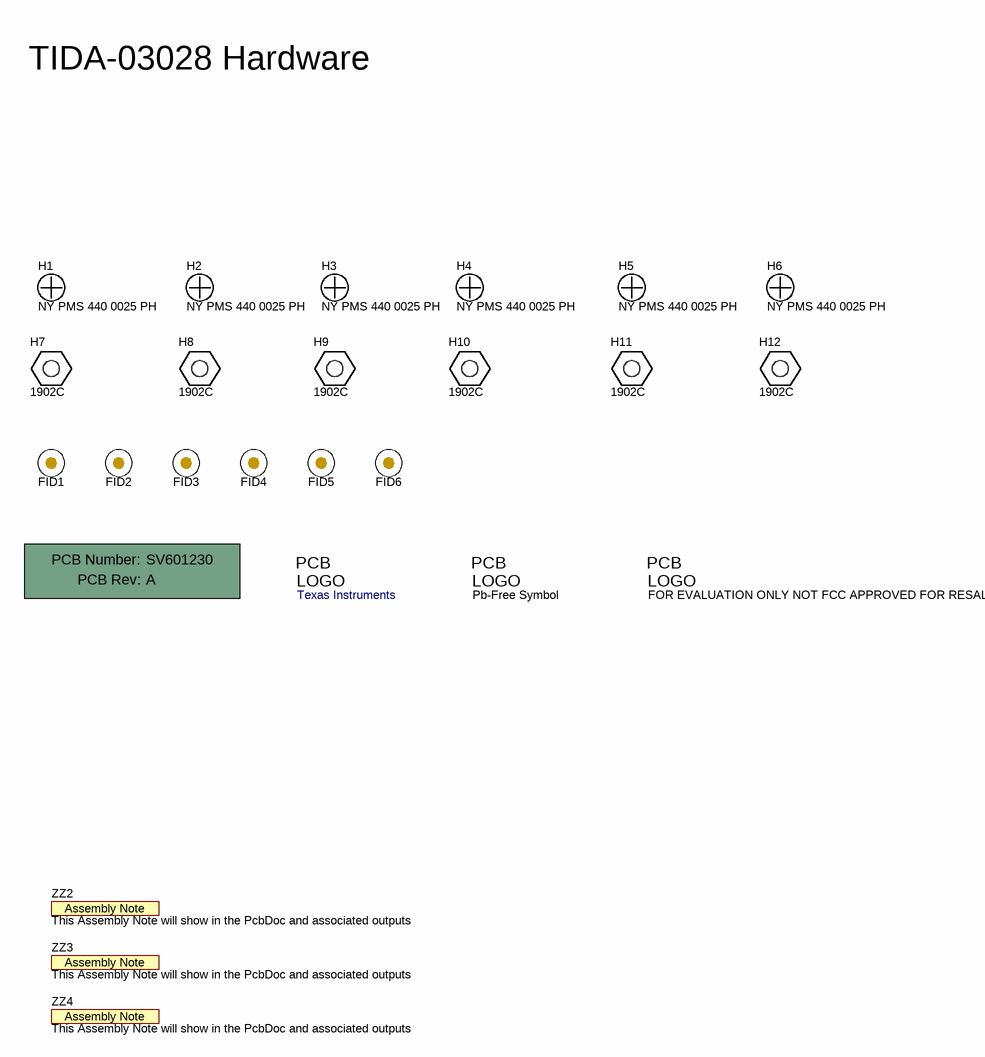
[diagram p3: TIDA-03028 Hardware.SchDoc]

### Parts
!PCB  Printed Circuit Board  (value not drawn)  (mechanical)
FID1  Fiducial  [Fiducial10-30]  (value not drawn)
FID2  Fiducial  [Fiducial10-30]  (value not drawn)
FID3  Fiducial  [Fiducial10-30]  (value not drawn)
FID4  Fiducial  [Fiducial10-30]  (value not drawn)
FID5  Fiducial  [Fiducial10-30]  (value not drawn)
FID6  Fiducial  [Fiducial10-30]  (value not drawn)
H1  NY PMS 440 0025 PH  [NY PMS 440 0025 PH]
H2  NY PMS 440 0025 PH  [NY PMS 440 0025 PH]
H3  NY PMS 440 0025 PH  [NY PMS 440 0025 PH]
H4  NY PMS 440 0025 PH  [NY PMS 440 0025 PH]
H5  NY PMS 440 0025 PH  [NY PMS 440 0025 PH]
H6  NY PMS 440 0025 PH  [NY PMS 440 0025 PH]
H7  1902C  [Keystone_1902C]
H8  1902C  [Keystone_1902C]
H9  1902C  [Keystone_1902C]
H10  1902C  [Keystone_1902C]
H11  1902C  [Keystone_1902C]
H12  1902C  [Keystone_1902C]
Logo1  Texas Instruments  [TI_Stacked_SolderMask_Medium]  (no BOM)
Logo2  Pb-Free Symbol  [Pb-Free_Overlay_Small]  (no BOM)
Logo3  FOR EVALUATION ONLY NOT FCC APPROVED FOR RESALE  [Pb-Free_Overlay_Small]  (no BOM)
ZZ2  This Assembly Note will show in the PcbDoc and associated outputs  [AssemblyNote]  (no BOM)
ZZ3  This Assembly Note will show in the PcbDoc and associated outputs  [AssemblyNote]  (no BOM)
ZZ4  This Assembly Note will show in the PcbDoc and associated outputs  [AssemblyNote]  (no BOM)

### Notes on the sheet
- TIDA-03028 Hardware

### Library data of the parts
!PCB = PCB: Manufacturer: Any; PartNumber: SV601230; SymbolCreator: a0414036
FID1-FID6 = Fiducial: Fiducial mark.  There is nothing to buy or mount.; SymbolCreator: codlsc
H1-H6 = NY PMS 440 0025 PH: Machine Screw, Round, #4-40 x 1/4, Nylon, Philips panhead; Manufacturer: B&F Fastener Supply; CompType: Hardware; SymbolCreator: codlsc; U/M: EA
H7-H12 = 1902C: Standoff, Hex, 0.5"L #4-40 Nylon; Manufacturer: Keystone; CompType: Hardware; SymbolCreator: a0412235
Logo1 = TI_Logo: Texas Instrument Corporate Signature; SymbolCreator: a0412235
Logo2 = Pb-Free: SymbolCreator: a0412235
Logo3 = Pb-Free: Pb-Free Symbol; SymbolCreator: a0412235
ZZ2-ZZ4 = AssemblyNote: SymbolCreator: codlsc

## Sheet TIDA-03028 Block Diagram.SchDoc: TIDA-03028 Block Diagram
size 431 x 279 mm; Date: Not shown in title block; ApprovedBy: Not shown in title block; CheckedBy: Not shown in title block; Author: Not shown in title block; CompanyName: Not shown in title block; Engineer: Not shown in title block; Organization: Not shown in title block; Address1: Not shown in title block; Address2: Not shown in title block; Address3: Not shown in title block; Address4: Not shown in title block; DocumentNumber: 1; Revision: Use project parameter SCH_Rev; SheetNumber: 1; SheetTotal: 6; PageSetup: Record=PageOptions¦CenterHorizontal=True¦CenterVertical=True¦PrintScale=1.00¦XCorrection=1.00¦YCorrection=1.00¦PrintKind=0¦BorderSize=5000000¦LeftOffset=0¦BottomOffset=0¦Orientation=2¦PaperLength=1000¦PaperWidth=1000¦Scale=100¦PaperSource=15¦PrintQuality=600¦MediaType=1¦DitherType=10¦PaperKind=Letter¦PrintScaleMode=1
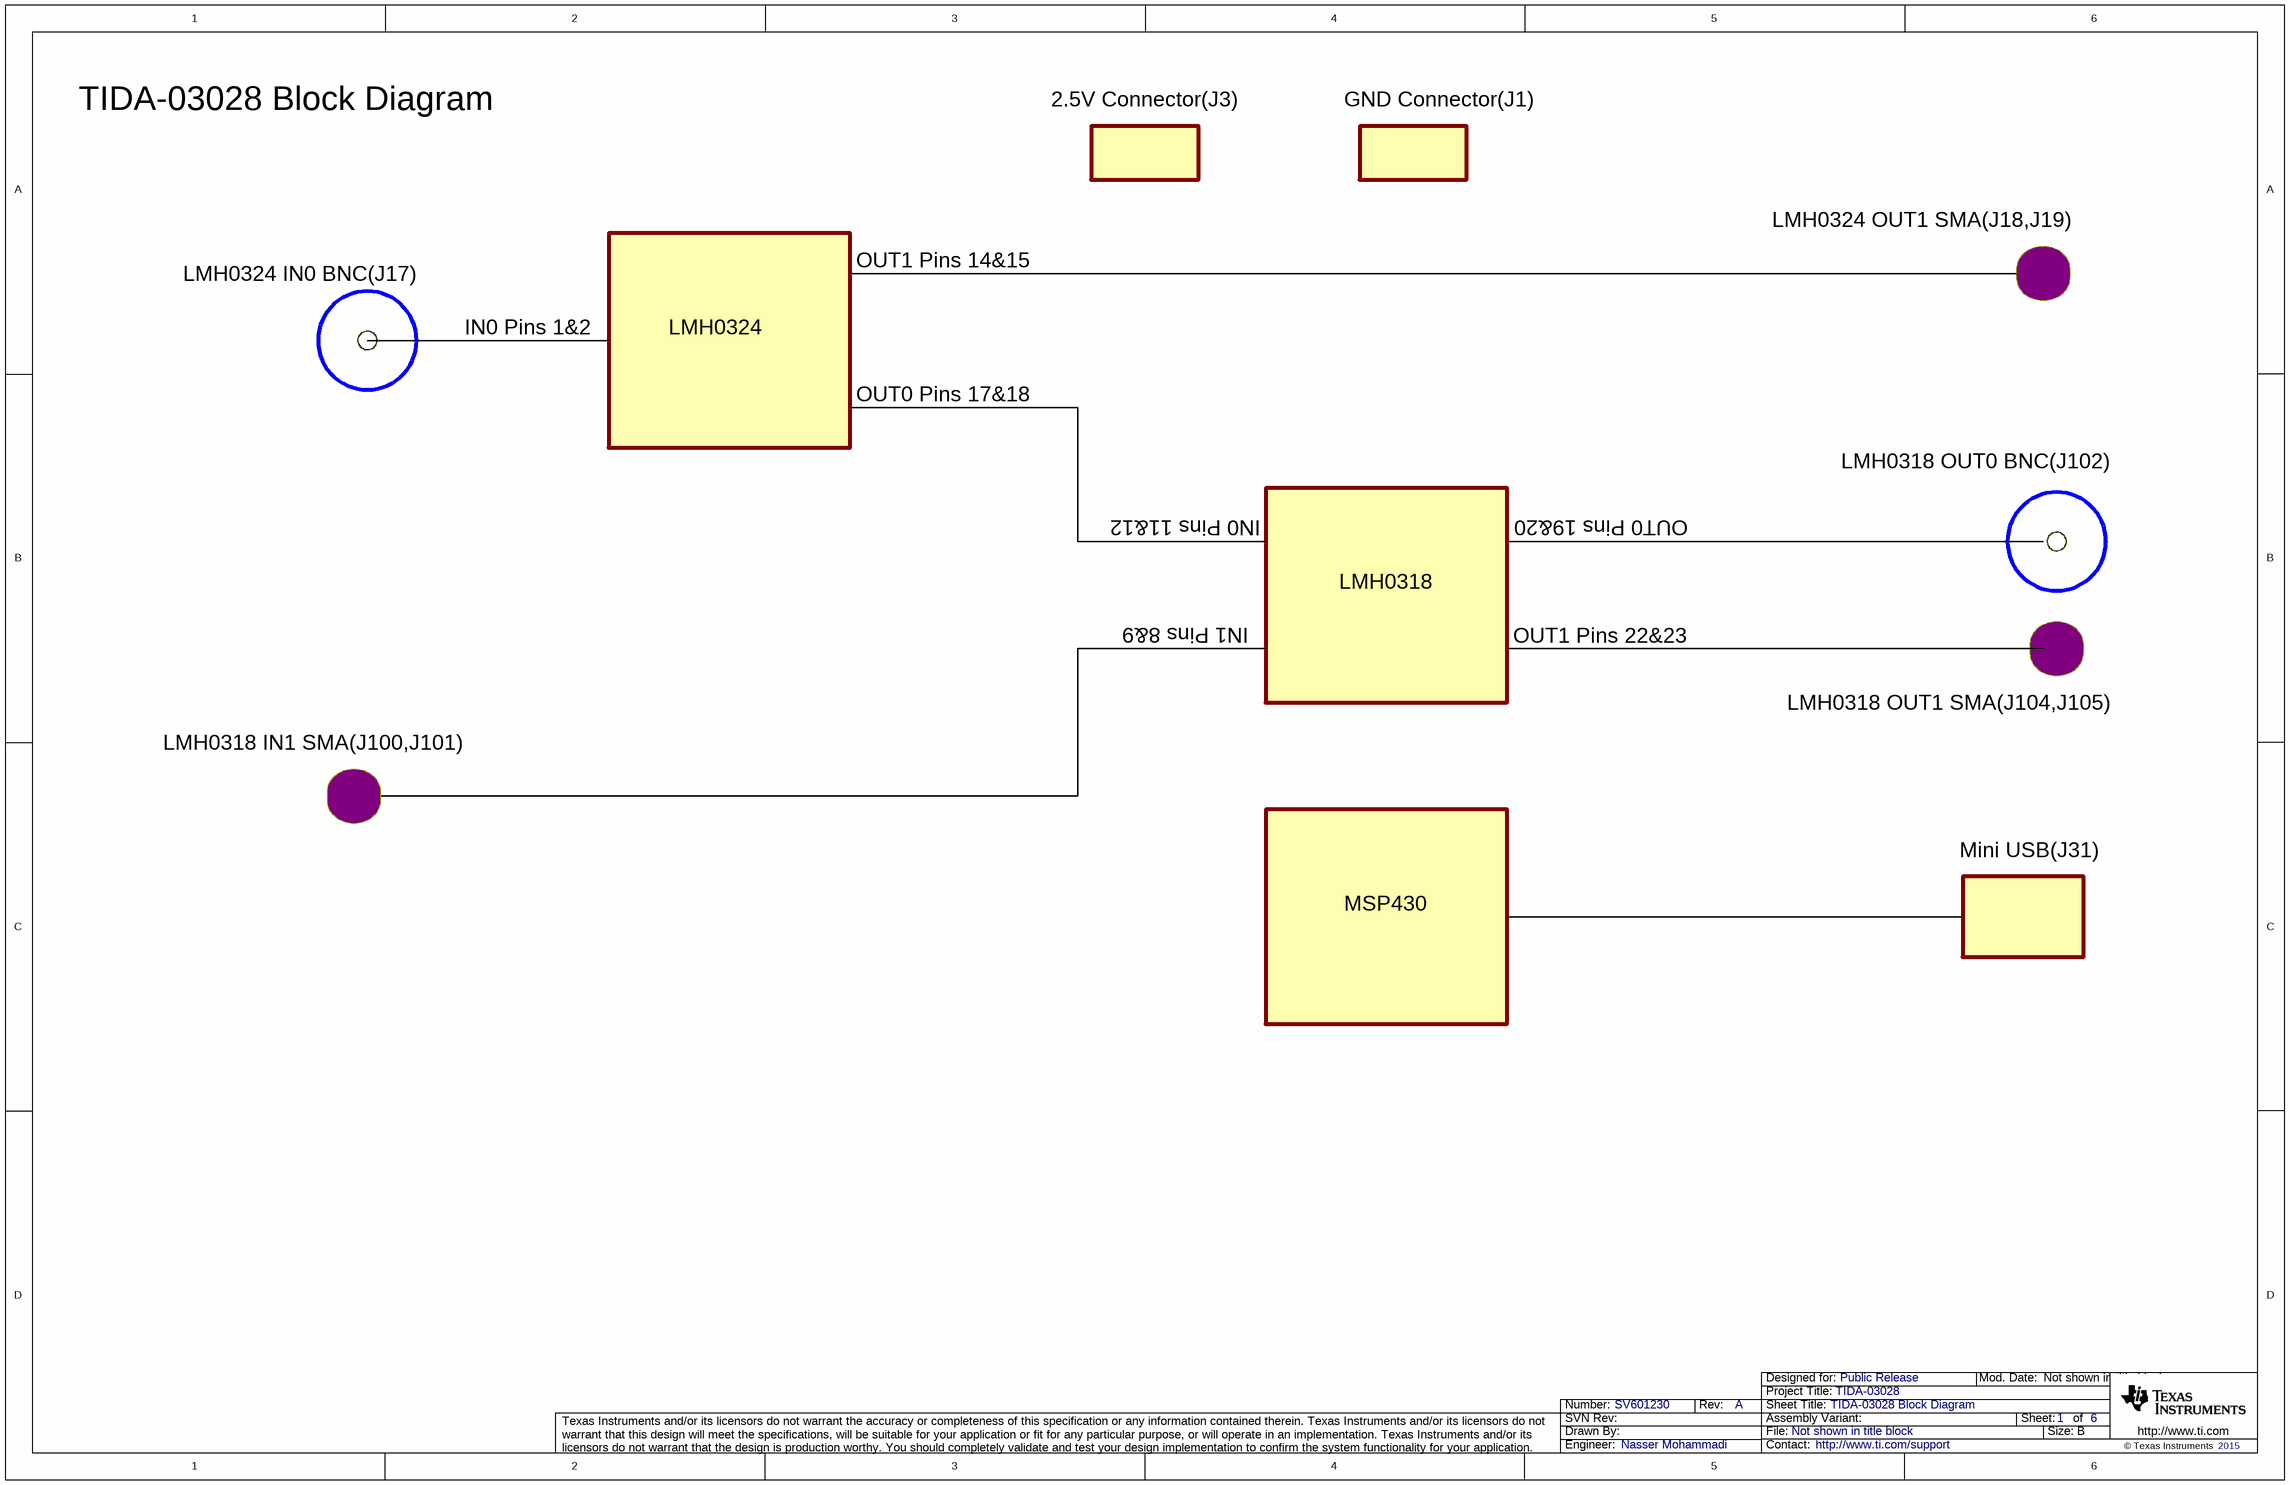
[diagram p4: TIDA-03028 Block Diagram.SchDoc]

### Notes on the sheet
- TIDA-03028 Block Diagram
- 2.5V Connector(J3)
- GND Connector(J1)
- LMH0324 OUT1 SMA(J18,J19)
- LMH0324 IN0 BNC(J17)
- OUT1 Pins 14&15
- IN0 Pins 1&2
- LMH0324
- OUT0 Pins 17&18
- LMH0318 OUT0 BNC(J102)
- IN0 Pins 11&12
- OUT0 Pins 19&20
- IN1 Pins 8&9
- LMH0318
- OUT1 Pins 22&23
- LMH0318 OUT1 SMA(J104,J105)
- LMH0318 IN1 SMA(J100,J101)
- MSP430
- Mini USB(J31)

## Sheet TIDA-03028 Power.SchDoc: TIDA-03028 Power
size 431 x 279 mm; Date: Not shown in title block; ApprovedBy: Not shown in title block; CheckedBy: Not shown in title block; Author: Not shown in title block; CompanyName: Not shown in title block; Engineer: Not shown in title block; Organization: Not shown in title block; Address1: Not shown in title block; Address2: Not shown in title block; Address3: Not shown in title block; Address4: Not shown in title block; DocumentNumber: 1; Revision: Use project parameter SCH_Rev; SheetNumber: 5; SheetTotal: 6; PageSetup: Record=PageOptions¦CenterHorizontal=True¦CenterVertical=True¦PrintScale=1.00¦XCorrection=1.00¦YCorrection=1.00¦PrintKind=0¦BorderSize=5000000¦LeftOffset=0¦BottomOffset=0¦Orientation=2¦PaperLength=1000¦PaperWidth=1000¦Scale=100¦PaperSource=15¦PrintQuality=600¦MediaType=1¦DitherType=10¦PaperKind=Letter¦PrintScaleMode=1
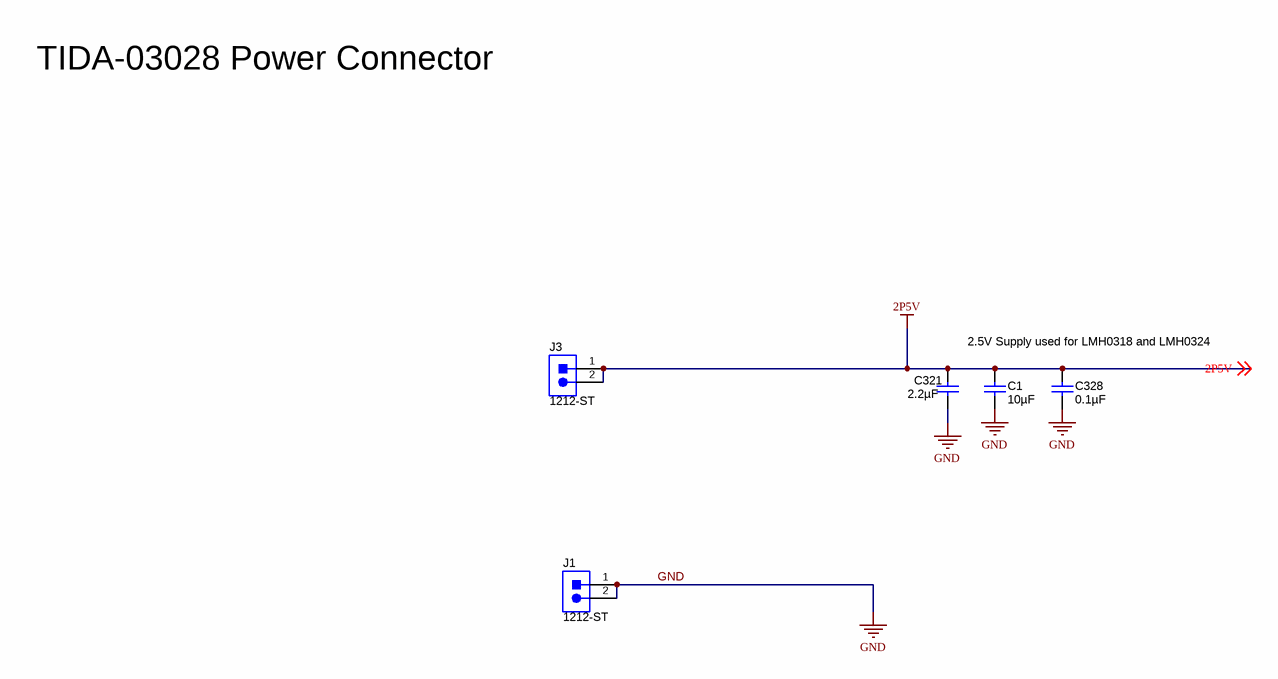
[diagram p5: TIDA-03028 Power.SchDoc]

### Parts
C1  ValueDisplayed: 10µF  [0805_HV]  (hidden comment: 0805YD106MAT2A)
C321  ValueDisplayed: 2.2µF  [C0805]  (hidden comment: 0805YD225KAT2A)
C328  ValueDisplayed: 0.1µF  [0402]  (hidden comment: C1005X5R0J104K)
J1  1212-ST  [Keystone_1212-ST]
J3  1212-ST  [Keystone_1212-ST]

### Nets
2P5V: C1.1 C321.2 C328.1 J3.1 J3.2 ; off-sheet 2P5V
GND: C1.2 C321.1 C328.2 J1.1 J1.2

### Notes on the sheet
- TIDA-03028 Power Connector
- 2.5V Supply used for LMH0318 and LMH0324

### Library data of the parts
C1 = 0805YD106MAT2A: CAP, CERM, 10uF, 16V, +/-20%, X5R, 0805; Manufacturer: AVX; Polarized: N; CompType: Capacitor; U/M: EA; Cap_F: 0.00001; Tolerance_%: 20; Value1: Unknown; VDC_V: 16; TaMin_C: -55; TaMax_C: 85; Cap_Case: 0805
C321 = 0805YD225KAT2A: as C21 on sheet TIDA-03028 USB_CNTRL
C328 = C1005X5R0J104K: as C5 on sheet TIDA-03028 LMH0324_Schematic
J1 J3 = 1212-ST: Disconnect Terminal, 5.08mm, 2x1, Tin, TH; Manufacturer: Keystone; SymbolCreator: a0412235; U/M: EA

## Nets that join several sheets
2P5V: TIDA-03028 LMH0324_Schematic (10 pins), TIDA-03028 LMH0318_Schematic (6 pins), TIDA-03028 Power (5 pins)
GND: TIDA-03028 LMH0324_Schematic (28 pins), TIDA-03028 USB_CNTRL (29 pins), TIDA-03028 LMH0318_Schematic (30 pins), TIDA-03028 Power (5 pins)
USB_3P3V: TIDA-03028 LMH0324_Schematic (J8.5 R1.2 R2.2), TIDA-03028 USB_CNTRL (9 pins)
GPIO0/I2C_SDA: TIDA-03028 LMH0324_Schematic (J8.10 J9.1 U1.10), TIDA-03028 USB_CNTRL (U4.46), TIDA-03028 LMH0318_Schematic (U100.4)
GPIO1/I2C_SCL: TIDA-03028 LMH0324_Schematic (J8.9 J21.2 U1.21), TIDA-03028 USB_CNTRL (U4.47), TIDA-03028 LMH0318_Schematic (U100.3)
LMH0324_OUT0_M: TIDA-03028 LMH0324_Schematic (U1.17), TIDA-03028 LMH0318_Schematic (C101.2)
LMH0324_OUT0_P: TIDA-03028 LMH0324_Schematic (U1.18), TIDA-03028 LMH0318_Schematic (C100.2)

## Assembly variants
001: not fitted FID1 FID2 FID3 FID4 FID5 FID6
